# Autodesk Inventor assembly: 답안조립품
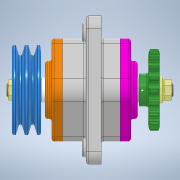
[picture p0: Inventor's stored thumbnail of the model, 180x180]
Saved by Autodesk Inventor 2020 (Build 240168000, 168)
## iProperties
Created: 2021-07
Part Number: 답안조립품
Document SubType Name: Assembly
Designer: Owner
Author: Owner
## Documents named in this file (16)
- C:\Users\Owner\Desktop\710707V1003\710707V1003\답안조립품.iam
- C:\Users\Owner\Desktop\710707V1003\710707V1003\본체.ipt
- C:\Users\Owner\Desktop\710707V1003\710707V1003\M16 너트.ipt
- C:\Users\Owner\Desktop\710707V1003\710707V1003\V-벨트풀리.ipt
- C:\Users\Owner\Desktop\710707V1003\710707V1003\멈춤나사 M4.ipt
- C:\Users\Owner\Desktop\710707V1003\710707V1003\베어링 6206.ipt
- C:\Users\Owner\Desktop\710707V1003\710707V1003\볼트 M6.ipt
- C:\Users\Owner\Desktop\710707V1003\710707V1003\부시.ipt
- C:\Users\Owner\Desktop\710707V1003\710707V1003\오일실 30x42x8.ipt
- C:\Users\Owner\Desktop\710707V1003\710707V1003\오일실 30x45x8.ipt
- C:\Users\Owner\Desktop\710707V1003\710707V1003\체인 스프로킷.ipt
- C:\Users\Owner\Desktop\710707V1003\710707V1003\축.ipt
- C:\Users\Owner\Desktop\710707V1003\710707V1003\커버A.ipt
- C:\Users\Owner\Desktop\710707V1003\710707V1003\커버B.ipt
- C:\Users\Owner\Desktop\710707V1003\710707V1003\키 6x6x18.ipt
- C:\Users\Owner\Desktop\710707V1003\710707V1003\키 6x6x20.ipt
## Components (3 placed, 2 different names)
1. M16 너트:1 — 각도:3
2. V-벨트풀리:1 — 각도:2
3. M16 너트:2 — 각도:4
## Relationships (3: Angle 3)
- 각도:2 [Angle]: V-벨트풀리:1
- 각도:3 [Angle]: M16 너트:1
- 각도:4 [Angle]: M16 너트:2
